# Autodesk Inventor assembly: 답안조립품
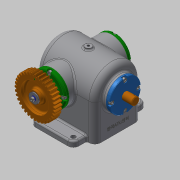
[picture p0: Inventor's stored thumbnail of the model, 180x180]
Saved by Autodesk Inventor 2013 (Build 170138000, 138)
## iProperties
Created: 2019-05
Part Number: 답안조립품
Document SubType Name: Assembly
Designer: Administrator
Mass: 2023.43 g
Surface Area: 1805.9 cm^2
Volume: 591.154 cm^3
Density: 3.42285 g/cm^3
Author: Administrator
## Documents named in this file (16)
- C:\Users\Administrator\Desktop\390504V1034\답안조립품.iam
- C:\Users\Administrator\Desktop\390504V1034\본체.ipt
- C:\Users\Administrator\Desktop\390504V1034\가이드부시.ipt
- C:\Users\Administrator\Desktop\390504V1034\베어링 6203.ipt
- C:\Users\Administrator\Desktop\390504V1034\볼트 M4x8.ipt
- C:\Users\Administrator\Desktop\390504V1034\볼트 M4x10.ipt
- C:\Users\Administrator\Desktop\390504V1034\스퍼기어.ipt
- C:\Users\Administrator\Desktop\390504V1034\스프링와셔.ipt
- C:\Users\Administrator\Desktop\390504V1034\슬라이더.ipt
- C:\Users\Administrator\Desktop\390504V1034\오일 실 17 32 8.ipt
- C:\Users\Administrator\Desktop\390504V1034\커버 A.ipt
- C:\Users\Administrator\Desktop\390504V1034\커버 B.ipt
- C:\Users\Administrator\Desktop\390504V1034\키 4x4x14.ipt
- C:\Users\Administrator\Desktop\390504V1034\편심축.ipt
- C:\Users\Administrator\Desktop\390504V1034\평와셔.ipt
- C:\Users\Administrator\Desktop\390504V1034\가변스프링.ipt
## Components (2 placed, 2 different names)
1. 가이드부시:1
2. 가변스프링:1
